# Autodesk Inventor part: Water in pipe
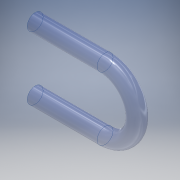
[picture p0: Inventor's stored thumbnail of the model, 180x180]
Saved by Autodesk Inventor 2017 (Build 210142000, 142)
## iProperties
Created: 2020-03
Part Number: Water in pipe
Material: Water
Document SubType Name: Modeling
Designer: user
Density: 0.9983 g/cm^3
Appearance: Tropical Blue
Author: user
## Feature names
1. Sweep1
## Parameters: d1 = 25 mm, d2 = 55 mm, d3 = 55 mm, d4 = 12.5 mm, d5 = 0, d6 = 0
